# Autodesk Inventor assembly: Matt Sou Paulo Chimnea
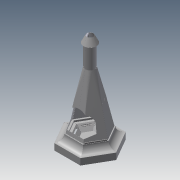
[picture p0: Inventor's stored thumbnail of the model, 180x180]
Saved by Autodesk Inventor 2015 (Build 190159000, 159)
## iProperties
Created: 2014-12
Part Number: Matt Sou Paulo Chimnea
Document SubType Name: Assembly
Designer: rsheridan
Author: rsheridan
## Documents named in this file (6)
- C:\Users\TREINA6\Desktop\#46- Sheet Metal Technology\WSC2015_TP46_pre\Sheet Metal\Matt Sou Paulo Chimnea.iam
- C:\Users\TREINA6\Desktop\#46- Sheet Metal Technology\WSC2015_TP46_pre\Sheet Metal\Base Assembly.iam
- C:\Users\TREINA6\Desktop\#46- Sheet Metal Technology\WSC2015_TP46_pre\Sheet Metal\Upper_Assy.iam
- C:\Users\TREINA6\Desktop\#46- Sheet Metal Technology\WSC2015_TP46_pre\Sheet Metal\RivNut.ipt
- C:\Users\TREINA6\Desktop\#46- Sheet Metal Technology\WSC2015_TP46_pre\Sheet Metal\ANSI B18.6.7M - M5x0.8 x 6(4).ipt
- C:\Users\TREINA6\Desktop\#46- Sheet Metal Technology\WSC2015_TP46_pre\Sheet Metal\Body Assembly New.iam
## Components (11 placed, 5 different names)
1. Base Assembly:1 [sub-assembly] — Mate:1, Mate:2, Mate:3, Flush:1
2. Body Assembly New:1 [sub-assembly] — Mate:1, Mate:2, Mate:3, Mate:4, Mate:5, Insert:1
3. Upper_Assy:1 [sub-assembly] — Mate:4, Mate:5, Insert:2, Flush:1
4. RivNut:1 — Insert:1
5. ANSI B18.6.7M - M5x0.8 x 6(4):1 — Insert:2
6. RivNut:2
7. ANSI B18.6.7M - M5x0.8 x 6(4):2
8. RivNut:4
9. ANSI B18.6.7M - M5x0.8 x 6(4):4
10. RivNut:5
11. ANSI B18.6.7M - M5x0.8 x 6(4):5
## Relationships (8: Mate 5, Insert 2, Flush 1)
- Mate:1: Base Assembly:1 ↔ Body Assembly New:1
- Mate:2: Base Assembly:1 ↔ Body Assembly New:1
- Mate:3: Base Assembly:1 ↔ Body Assembly New:1
- Mate:4: Body Assembly New:1 ↔ Upper_Assy:1
- Mate:5: Body Assembly New:1 ↔ Upper_Assy:1
- Insert:1: Body Assembly New:1 ↔ RivNut:1
- Insert:2: Upper_Assy:1 ↔ ANSI B18.6.7M - M5x0.8 x 6(4):1
- Flush:1: Base Assembly:1 ↔ Upper_Assy:1
